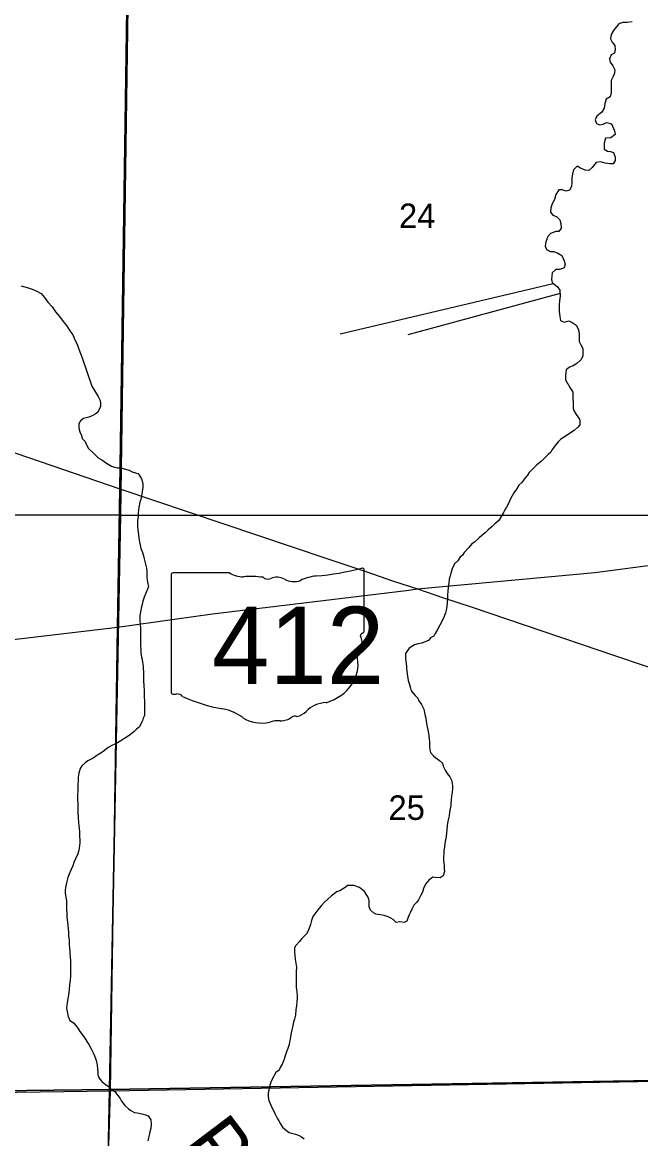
# Model space of a CAD drawing. Extents: x 1588073 to 2013523, y 1090242 to 1357120.
# Drawn here: x 1837534 to 1843112, y 1223082 to 1233146 of the extents above; entities that cross this region are included whole.
import ezdxf

# ---------------------------------------------------------------- set-up
doc = ezdxf.new("R2010")
doc.units = 0
for name, color, linetype in [('GM_X_Interstate_Route', 7, 'Continuous'), ('GM_X_Minor_River', 7, 'Continuous'), ('GM_X_Minor_River_Text', 7, 'Continuous'), ('GM_X_Section', 7, 'Continuous'), ('GM_X_Section_Text', 7, 'Continuous'), ('GM_X_State_Location', 7, 'Continuous'), ('GM_X_State_Route', 7, 'Continuous'), ('GM_X_State_Shield', 7, 'Continuous'), ('GM_X_Township_Road', 7, 'Continuous')]:
    doc.layers.add(name, color=color, linetype=linetype)

msp = doc.modelspace()

# ---------------------------------------------------------------- linework, layer by layer
at = {"layer": 'GM_X_Interstate_Route'}
for points in [[(1837380, 1229295), (1838415, 1228941)], [(1838415, 1228941), (1840282, 1228313), (1840633, 1228194), (1840882, 1228109), (1841098, 1228038)], [(1841098, 1228038), (1841332, 1227957), (1841584, 1227876), (1842884, 1227435), (1843133, 1227350), (1843672, 1227170), (1843934, 1227084), (1844383, 1226925), (1844677, 1226810), (1844858, 1226738), (1844970, 1226689), (1845260, 1226559), (1846118, 1226154), (1846502, 1225974), (1846992, 1225774), (1847538, 1225582), (1847787, 1225501), (1848246, 1225375), (1848392, 1225337), (1848857, 1225234), (1849384, 1225139), (1849541, 1225117), (1850303, 1224995), (1853825, 1224444)]]:
    msp.add_lwpolyline(points, dxfattribs=at)
at = {"layer": 'GM_X_Minor_River'}
for p, q in [((1840401, 1230338), (1842324, 1230792)), ((1842385, 1230702), (1841013, 1230328))]:
    msp.add_line(p, q, dxfattribs=at)
for points in [[(1843035, 1233151), (1842991, 1233145), (1842950, 1233145), (1842914, 1233133), (1842867, 1233072), (1842845, 1233036), (1842841, 1232998), (1842855, 1232968), (1842879, 1232938), (1842882, 1232900), (1842876, 1232868), (1842846, 1232852), (1842832, 1232815), (1842836, 1232785), (1842862, 1232753), (1842878, 1232717), (1842877, 1232687), (1842863, 1232657), (1842847, 1232621), (1842845, 1232579), (1842847, 1232545), (1842845, 1232513), (1842836, 1232474), (1842800, 1232452), (1842790, 1232414), (1842784, 1232372), (1842762, 1232336), (1842716, 1232300), (1842702, 1232267), (1842713, 1232235), (1842741, 1232223), (1842773, 1232228), (1842805, 1232242), (1842849, 1232230), (1842877, 1232166), (1842883, 1232134), (1842843, 1232104), (1842795, 1232101), (1842784, 1232055), (1842782, 1232001), (1842812, 1231985), (1842840, 1231981), (1842868, 1231971), (1842882, 1231929), (1842881, 1231901), (1842863, 1231871), (1842835, 1231869), (1842793, 1231877), (1842750, 1231887), (1842710, 1231882), (1842674, 1231838), (1842643, 1231810), (1842612, 1231814), (1842570, 1231832), (1842538, 1231848), (1842506, 1231817), (1842496, 1231777), (1842491, 1231747), (1842491, 1231703), (1842489, 1231665), (1842471, 1231633), (1842439, 1231623), (1842405, 1231635), (1842373, 1231636), (1842347, 1231594), (1842335, 1231548), (1842315, 1231508), (1842302, 1231472), (1842298, 1231434), (1842320, 1231406), (1842352, 1231394), (1842384, 1231366), (1842392, 1231332), (1842395, 1231290), (1842375, 1231259), (1842347, 1231259), (1842299, 1231243), (1842273, 1231215), (1842255, 1231167), (1842251, 1231127), (1842263, 1231099), (1842300, 1231079), (1842330, 1231081), (1842364, 1231065), (1842402, 1231045), (1842422, 1230995), (1842432, 1230965), (1842423, 1230931), (1842383, 1230917)], [(1842383, 1230917), (1842348, 1230918), (1842315, 1230886), (1842307, 1230828), (1842313, 1230800), (1842361, 1230762), (1842383, 1230730), (1842386, 1230678), (1842380, 1230636), (1842378, 1230600), (1842378, 1230568), (1842376, 1230540), (1842383, 1230495), (1842389, 1230459), (1842421, 1230443), (1842465, 1230454), (1842493, 1230440), (1842529, 1230416), (1842552, 1230378), (1842556, 1230334), (1842558, 1230306), (1842556, 1230267), (1842572, 1230239), (1842589, 1230205), (1842591, 1230163), (1842589, 1230135), (1842573, 1230103), (1842535, 1230071), (1842503, 1230049), (1842469, 1230037), (1842441, 1230014), (1842435, 1229962), (1842434, 1229924), (1842480, 1229844)], [(1837523, 1230771), (1837579, 1230755), (1837624, 1230739), (1837666, 1230723), (1837704, 1230700), (1837736, 1230664), (1837766, 1230624), (1837803, 1230580), (1837833, 1230536), (1837869, 1230494), (1837904, 1230450), (1837932, 1230414), (1837962, 1230364), (1837990, 1230328), (1838009, 1230282), (1838029, 1230244), (1838045, 1230200), (1838059, 1230159), (1838074, 1230121), (1838161, 1229865)], [(1838161, 1229865), (1838218, 1229774), (1838236, 1229736), (1838240, 1229710), (1838240, 1229682), (1838215, 1229630), (1838193, 1229614), (1838169, 1229600), (1838135, 1229585), (1838111, 1229581), (1838087, 1229573), (1838059, 1229553), (1838045, 1229527), (1838045, 1229497), (1838047, 1229475), (1838053, 1229453), (1838067, 1229420), (1838075, 1229394), (1838100, 1229366), (1838114, 1229338), (1838130, 1229304), (1838182, 1229257), (1838219, 1229219), (1838251, 1229203), (1838293, 1229171), (1838339, 1229145), (1838367, 1229135), (1838397, 1229131), (1838426, 1229129), (1838452, 1229121), (1838498, 1229108), (1838526, 1229094), (1838556, 1229086), (1838580, 1229078), (1838608, 1229030), (1838619, 1229000), (1838621, 1228978), (1838621, 1228956), (1838619, 1228934), (1838609, 1228874), (1838603, 1228845), (1838593, 1228819), (1838586, 1228773), (1838582, 1228747), (1838580, 1228723), (1838578, 1228689), (1838574, 1228659), (1838572, 1228631), (1838572, 1228603), (1838575, 1228570), (1838581, 1228530), (1838585, 1228496), (1838591, 1228460), (1838597, 1228432), (1838604, 1228402), (1838614, 1228376), (1838626, 1228336), (1838634, 1228310), (1838644, 1228272), (1838650, 1228250), (1838655, 1228226), (1838657, 1228196), (1838659, 1228162), (1838659, 1228140), (1838661, 1228118), (1838667, 1228084), (1838673, 1228061), (1838664, 1228035), (1838650, 1228001), (1838632, 1227965), (1838622, 1227927), (1838614, 1227897), (1838606, 1227865), (1838600, 1227830), (1838595, 1227798), (1838595, 1227750), (1838597, 1227720), (1838601, 1227682), (1838601, 1227620), (1838600, 1227586), (1838600, 1227524), (1838602, 1227494), (1838604, 1227461), (1838610, 1227423), (1838615, 1227401), (1838619, 1227379), (1838625, 1227341), (1838625, 1227319), (1838627, 1227295), (1838628, 1227211), (1838630, 1227165), (1838632, 1227121), (1838634, 1227088), (1838634, 1227066), (1838637, 1227030), (1838635, 1226982), (1838635, 1226950), (1838635, 1226918), (1838635, 1226896), (1838625, 1226872), (1838617, 1226850)], [(1842476, 1229852), (1842499, 1229811), (1842501, 1229777), (1842501, 1229751), (1842503, 1229718), (1842503, 1229690), (1842502, 1229668), (1842508, 1229646), (1842530, 1229610), (1842560, 1229568), (1842562, 1229546), (1842564, 1229518), (1842545, 1229496), (1842513, 1229466), (1842487, 1229450), (1842441, 1229419), (1842391, 1229387), (1842367, 1229365), (1842345, 1229333), (1842315, 1229294), (1842303, 1229272), (1842277, 1229250), (1842237, 1229212), (1842215, 1229186), (1842175, 1229157), (1842106, 1229087), (1842092, 1229065), (1842060, 1229026), (1842040, 1228998), (1842012, 1228974), (1841992, 1228936), (1841968, 1228904), (1841938, 1228849), (1841919, 1228809), (1841901, 1228775), (1841887, 1228751), (1841875, 1228727), (1841855, 1228690), (1841833, 1228656), (1841797, 1228624), (1841771, 1228602), (1841737, 1228570), (1841708, 1228545), (1841680, 1228519), (1841656, 1228499), (1841614, 1228459), (1841588, 1228444), (1841562, 1228410), (1841520, 1228366), (1841504, 1228342), (1841482, 1228322), (1841462, 1228291), (1841434, 1228263), (1841411, 1228219), (1841399, 1228181), (1841395, 1228157), (1841385, 1228127), (1841381, 1228090), (1841379, 1228068), (1841373, 1228024), (1841370, 1227976), (1841370, 1227952), (1841368, 1227918), (1841364, 1227880), (1841358, 1227846), (1841350, 1227824), (1841339, 1227791), (1841329, 1227767), (1841301, 1227711), (1841277, 1227665), (1841259, 1227637), (1841247, 1227612), (1841217, 1227596), (1841197, 1227574), (1841159, 1227558), (1841137, 1227548), (1841105, 1227544), (1841073, 1227533), (1841025, 1227505), (1840991, 1227457), (1840990, 1227415), (1840994, 1227387), (1841000, 1227342), (1841000, 1227318), (1841006, 1227274), (1841015, 1227214), (1841023, 1227186), (1841035, 1227144), (1841043, 1227118), (1841078, 1227078), (1841102, 1227052), (1841112, 1227030), (1841136, 1226996), (1841156, 1226954), (1841167, 1226894), (1841173, 1226872), (1841181, 1226826), (1841187, 1226794), (1841191, 1226768), (1841198, 1226736), (1841204, 1226690)], [(1838617, 1226850), (1838607, 1226828), (1838592, 1226795), (1838564, 1226773), (1838542, 1226753), (1838510, 1226725), (1838480, 1226705), (1838450, 1226686), (1838424, 1226670), (1838394, 1226650), (1838368, 1226640), (1838342, 1226628), (1838310, 1226608), (1838276, 1226583), (1838244, 1226559), (1838208, 1226537), (1838174, 1226513), (1838150, 1226500), (1838124, 1226488), (1838100, 1226470), (1838070, 1226442), (1838056, 1226420), (1838043, 1226378), (1838039, 1226342), (1838037, 1226307), (1838035, 1226279), (1838035, 1226253), (1838035, 1226213), (1838033, 1226189), (1838034, 1226053), (1838036, 1226025), (1838037, 1225976), (1838041, 1225934), (1838043, 1225902), (1838047, 1225876), (1838049, 1225854), (1838051, 1225830), (1838051, 1225808), (1838054, 1225774), (1838054, 1225750), (1838048, 1225702), (1838042, 1225672), (1838034, 1225650), (1838014, 1225605), (1838000, 1225573), (1837989, 1225543), (1837975, 1225509), (1837963, 1225483), (1837945, 1225438), (1837935, 1225400), (1837929, 1225374), (1837925, 1225346), (1837922, 1225324), (1837920, 1225302), (1837924, 1225274), (1837930, 1225244), (1837934, 1225222), (1837934, 1225182), (1837932, 1225150), (1837935, 1225111), (1837937, 1225079), (1837945, 1225011), (1837950, 1224939), (1837952, 1224911), (1837956, 1224873), (1837958, 1224829), (1837960, 1224801), (1837962, 1224773), (1837962, 1224751), (1837967, 1224721), (1837969, 1224682), (1837970, 1224548), (1837966, 1224510), (1837960, 1224470), (1837956, 1224426), (1837950, 1224375), (1837946, 1224347), (1837939, 1224307), (1837937, 1224283), (1837933, 1224259), (1837941, 1224213), (1837949, 1224185), (1837964, 1224149), (1837996, 1224127), (1838030, 1224087), (1838054, 1224049), (1838074, 1224023), (1838097, 1223987), (1838117, 1223959), (1838135, 1223931), (1838151, 1223899), (1838165, 1223873), (1838180, 1223843), (1838192, 1223815), (1838202, 1223787), (1838210, 1223749), (1838214, 1223709), (1838216, 1223683), (1838215, 1223657), (1838229, 1223629), (1838253, 1223599)], [(1841204, 1226690), (1841206, 1226656), (1841206, 1226625), (1841210, 1226587), (1841216, 1226565), (1841239, 1226537), (1841263, 1226515), (1841297, 1226491), (1841323, 1226466), (1841331, 1226441), (1841349, 1226405), (1841368, 1226375), (1841392, 1226343), (1841406, 1226313), (1841412, 1226291), (1841414, 1226261), (1841414, 1226235), (1841411, 1226207), (1841407, 1226171), (1841403, 1226133), (1841399, 1226107), (1841399, 1226085), (1841389, 1226027), (1841386, 1225992), (1841376, 1225956), (1841370, 1225928), (1841368, 1225904), (1841364, 1225870), (1841357, 1225806), (1841351, 1225776), (1841345, 1225742), (1841343, 1225711), (1841337, 1225677), (1841335, 1225653), (1841333, 1225623), (1841334, 1225589), (1841338, 1225545), (1841340, 1225513), (1841342, 1225491), (1841330, 1225453), (1841304, 1225434), (1841258, 1225438), (1841236, 1225440), (1841200, 1225414), (1841170, 1225376), (1841152, 1225339), (1841145, 1225305), (1841129, 1225277), (1841107, 1225235), (1841093, 1225213), (1841067, 1225187), (1841047, 1225152), (1841037, 1225124), (1841023, 1225100), (1841011, 1225070), (1841004, 1225044), (1840980, 1225032), (1840939, 1225036), (1840905, 1225031), (1840879, 1225057), (1840857, 1225071), (1840835, 1225083), (1840797, 1225093), (1840765, 1225101), (1840723, 1225105), (1840701, 1225119), (1840676, 1225143), (1840664, 1225171), (1840664, 1225225), (1840658, 1225253), (1840642, 1225279), (1840621, 1225311), (1840577, 1225347), (1840525, 1225365), (1840469, 1225366), (1840445, 1225346), (1840397, 1225318), (1840369, 1225308), (1840345, 1225287), (1840323, 1225273), (1840289, 1225241), (1840259, 1225213), (1840233, 1225185), (1840199, 1225144), (1840173, 1225110), (1840156, 1225084), (1840144, 1225048), (1840134, 1225014), (1840116, 1224961), (1840098, 1224929), (1840054, 1224883), (1840036, 1224859), (1840001, 1224825), (1839989, 1224802), (1839989, 1224768), (1839991, 1224738), (1839995, 1224702), (1840008, 1224630), (1840006, 1224588), (1840006, 1224556), (1840004, 1224510)], [(1840004, 1224510), (1840006, 1224488), (1840006, 1224449), (1840009, 1224427), (1840011, 1224403), (1840013, 1224373), (1840013, 1224349), (1840011, 1224317), (1840009, 1224281), (1840003, 1224247), (1839998, 1224197), (1839988, 1224159), (1839980, 1224134), (1839972, 1224088), (1839964, 1224064), (1839960, 1224036), (1839953, 1224004), (1839951, 1223978), (1839945, 1223954), (1839941, 1223932), (1839929, 1223896), (1839921, 1223873), (1839907, 1223839), (1839895, 1223799), (1839888, 1223775), (1839878, 1223753), (1839860, 1223723), (1839852, 1223701), (1839822, 1223678), (1839788, 1223620), (1839776, 1223592), (1839768, 1223566), (1839759, 1223524), (1839753, 1223492), (1839753, 1223461), (1839757, 1223427), (1839785, 1223363), (1839796, 1223341), (1839812, 1223309), (1839834, 1223267), (1839848, 1223243), (1839862, 1223217), (1839882, 1223187), (1839917, 1223155), (1839941, 1223139), (1839963, 1223133), (1839997, 1223122), (1840031, 1223110), (1840053, 1223100), (1840077, 1223080)], [(1838253, 1223599), (1838281, 1223575), (1838311, 1223553), (1838333, 1223533), (1838366, 1223511), (1838396, 1223471), (1838416, 1223445), (1838428, 1223421), (1838460, 1223381), (1838491, 1223351), (1838513, 1223335), (1838547, 1223319), (1838569, 1223315), (1838599, 1223309), (1838625, 1223304), (1838647, 1223296), (1838671, 1223288), (1838694, 1223252), (1838698, 1223210), (1838694, 1223178), (1838686, 1223145), (1838680, 1223115), (1838674, 1223089), (1838668, 1223063)]]:
    msp.add_lwpolyline(points, dxfattribs=at)
at = {"layer": 'GM_X_Section'}
for points in [[(1838499, 1234122), (1843801, 1234286), (1843703, 1228699), (1838419, 1228704)], [(1833261, 1234025), (1838499, 1234122), (1838419, 1228704), (1833158, 1228711)], [(1838419, 1228704), (1838321, 1223525), (1833069, 1223464), (1833158, 1228711)], [(1843703, 1228699), (1843590, 1223612), (1838321, 1223525), (1838419, 1228704)], [(1838321, 1223525), (1843590, 1223612), (1843467, 1218307), (1838217, 1218226)], [(1833069, 1223464), (1838321, 1223525), (1838217, 1218226), (1838105, 1218225), (1832922, 1218156)]]:
    msp.add_lwpolyline(points, close=True, dxfattribs=at)
at = {"layer": 'GM_X_State_Route'}
for points in [[(1837979, 1210040), (1837985, 1212953), (1838096, 1218216), (1838170, 1218318), (1838201, 1218383), (1838249, 1220869), (1838331, 1223513), (1838394, 1227694), (1838415, 1228941), (1838488, 1234093), (1838626, 1242044)], [(1840996, 1228025), (1841098, 1228038), (1842697, 1228186), (1843683, 1228316), (1846708, 1228699), (1848882, 1228992), (1851497, 1229297), (1851555, 1229304), (1852872, 1229466), (1853498, 1229543), (1854181, 1229630)], [(1838394, 1227694), (1839249, 1227814), (1840996, 1228025)], [(1833152, 1227070), (1833234, 1227082), (1838394, 1227694)]]:
    msp.add_lwpolyline(points, dxfattribs=at)
at = {"layer": 'GM_X_State_Shield'}
for p, q in [((1840617, 1227656), (1840617, 1228209)), ((1838877, 1228164), (1838877, 1227108)), ((1839404, 1228182), (1838894, 1228182)), ((1840617, 1227656), (1840617, 1227656))]:
    msp.add_line(p, q, dxfattribs=at)
for centre, major_axis, start_param, end_param in [((1839997, 1229623), (1845, 0), 4.814394, 5.042369), ((1840598, 1228211), (19.4, 0), 6.141152, 7.989035), ((1838897, 1228166), (20.2, 0), 1.712693, 3.28349), ((1839525, 1228305), (196, 0), 4.042523, 4.731795), ((1839590, 1227589), (702, 0), 1.404758, 1.657858), ((1839749, 1228172), (56.4, 0), 3.836095, 5.185415), ((1839832, 1228050), (117, 0), 0.950623, 2.079405), ((1839983, 1228217), (141, 0), 4.081561, 5.145723), ((1840233, 1227860), (371, 0), 1.699011, 2.107814), ((1840613, 1227615), (30, 0), 1.883978, 3.671073), ((1840422, 1227545), (180, 0), 5.934695, 6.695948), ((1840596, 1227654), (20.7, 0), 5.05454, 6.418171), ((1840686, 1227425), (131, 0), 2.387724, 3.262537), ((1840101, 1227354), (462, 0), 5.101752, 6.440018), ((1838897, 1227105), (20.3, 0), 3.00124, 4.508301), ((1838932, 1227047), (56, 0), 0.519207, 1.627899), ((1838900, 1227213), (155, 0), 4.665946, 4.897461), ((1839638, 1227996), (1333, 0), 4.195997, 4.488961), ((1840295, 1226811), (253, 0), 1.647645, 2.488434), ((1839241, 1226633), (417, 0), 0.823519, 1.323587), ((1839992, 1226860), (39.7, 0), 1.147584, 2.315152), ((1839975, 1227005), (149, 0), 4.937069, 5.64225), ((1839692, 1227041), (265, 0), 4.026481, 4.996735), ((1839845, 1226676), (217, 0), 1.495662, 1.94098), ((1839864, 1226962), (141, 0), 4.691044, 5.507374)]:
    msp.add_ellipse(centre, major_axis=major_axis, ratio=0.8, start_param=start_param, end_param=end_param, dxfattribs=at)
at = {"layer": 'GM_X_Township_Road'}
for points in [[(1838331, 1223513), (1843596, 1223607)], [(1833047, 1223440), (1838331, 1223513)]]:
    msp.add_lwpolyline(points, dxfattribs=at)

# ---------------------------------------------------------------- texts
at = {"layer": 'GM_X_Minor_River_Text'}
msp.add_text('Pickerel', height=500.3, rotation=307.0019, dxfattribs=at).set_placement((1838981, 1223040))
at = {"layer": 'GM_X_Section_Text'}
for s, p in [('24', (1840932, 1231291)), ('25', (1840837, 1225956))]:
    msp.add_text(s, height=221, rotation=0, dxfattribs=at).set_placement(p)
at = {"layer": 'GM_X_State_Location'}
for s in ['s', 'r']:
    msp.add_text(s, height=1, dxfattribs=at).set_placement((1839727, 1227566))
msp.add_text('412', height=1, rotation=0, dxfattribs=at).set_placement((1839374, 1227493))
at = {"layer": 'GM_X_State_Shield'}
msp.add_text('412', height=696.1, dxfattribs=at).set_placement((1839246, 1227182))

doc.saveas('drawing.dxf')
